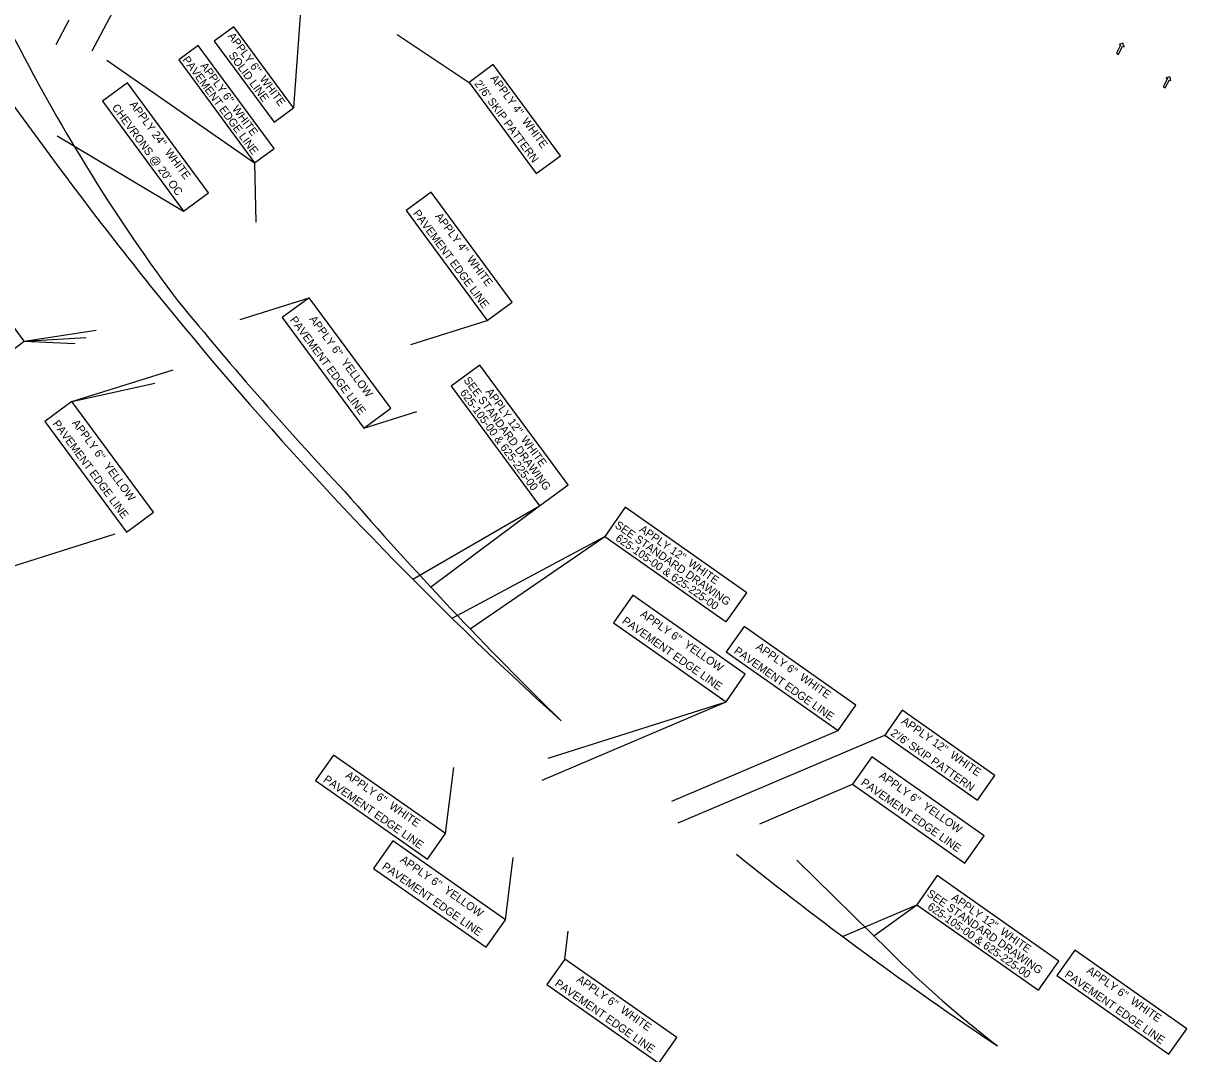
# Model space of a CAD drawing. Extents: x 1966013 to 1974896, y 789499 to 804826.
# Drawn here: x 1971229 to 1972392, y 795072 to 796102 of the extents above; entities that cross this region are included whole.
import ezdxf

# ---------------------------------------------------------------- set-up
doc = ezdxf.new("R2010")
doc.units = 0
for name, color, linetype in [('RD_EX_H2O_BlueLn', 7, 'Continuous'), ('RD_PD_ALT5_CL', 7, 'Continuous'), ('RD_PD_Final_Cl', 7, 'Continuous'), ('RD_PD_Final_LnLine', 7, 'Continuous')]:
    doc.layers.add(name, color=color, linetype=linetype)

msp = doc.modelspace()

# ---------------------------------------------------------------- linework, layer by layer
at = {"layer": 'RD_EX_H2O_BlueLn'}
for p, q in [((1971510.5, 796174.4), (1971499.1, 796017.7)), ((1971297.7, 796074.5), (1971318, 796113.1)), ((1971261.7, 796081), (1971274.7, 796105.7)), ((1971602.8, 796091.1), (1971674.5, 796043.1)), ((1971312.5, 796065.2), (1971460.2, 795962.6)), ((1971262.9, 795989.7), (1971389.1, 795914.2)), ((1971460.2, 795962.6), (1971461.4, 795903.2)), ((1971445.6, 795806.1), (1971514.7, 795827.8)), ((1971616.4, 795780.9), (1971692.7, 795804.9)), ((1971230, 795784.3), (1971301.7, 795795.5)), ((1971230, 795784.3), (1971291.8, 795788.1)), ((1971230, 795784.3), (1971280.7, 795782.2)), ((1971277.5, 795723.9), (1971378.9, 795755.8)), ((1971277.5, 795723.9), (1971360.6, 795742.4)), ((1971569.2, 795697.4), (1971622.3, 795714.1)), ((1971618.2, 795546.4), (1971744.8, 795619.8)), ((1971636.1, 795538.5), (1971744.8, 795619.8)), ((1971215.6, 795558.5), (1971320.9, 795591.6)), ((1971657.7, 795507.4), (1971810.1, 795589.2)), ((1971675.5, 795496.6), (1971810.1, 795589.2)), ((1971747.5, 795345.6), (1971931.4, 795423.9)), ((1971753.7, 795367.5), (1971931.4, 795423.9)), ((1971877.2, 795324.3), (1972043.3, 795395)), ((1971883.4, 795302.7), (1972089.9, 795390.6)), ((1971650.9, 795292), (1971659.2, 795358.1)), ((1971965.2, 795301.9), (1972057.7, 795341.3)), ((1971710.8, 795205.8), (1971718.7, 795268.2)), ((1972047.7, 795189.3), (1972121.9, 795220.9)), ((1972079, 795189.7), (1972121.9, 795220.9)), ((1971770.2, 795166.6), (1971773.7, 795194.4))]:
    msp.add_line(p, q, dxfattribs=at)
for points in [[(1971419.9, 796084.4), (1971479.7, 796003.4), (1971499.1, 796017.7), (1971439.3, 796098.8)], [(1971384.3, 796065.7), (1971460.2, 795962.6), (1971479.7, 795976.9), (1971403.7, 796080)], [(1971674.5, 796043.1), (1971741.7, 795951.9), (1971765.9, 795969.8), (1971698.7, 796061)], [(1971308, 796024.2), (1971389.1, 795914.2), (1971414.2, 795932.7), (1971333.1, 796042.7)], [(1971611.6, 795914.9), (1971692.7, 795804.9), (1971717.7, 795823.4), (1971636.6, 795933.4)], [(1971125.5, 795869.8), (1971203.1, 795764.5), (1971230, 795784.3), (1971152.4, 795889.6)], [(1971487.7, 795807.9), (1971569.2, 795697.4), (1971596.2, 795717.3), (1971514.7, 795827.8)], [(1971656.6, 795739.4), (1971744.8, 795619.8), (1971773.4, 795640.9), (1971685.2, 795760.4)], [(1971250.5, 795704.1), (1971332, 795593.5), (1971359, 795613.4), (1971277.5, 795723.9)], [(1971810.1, 795589.2), (1971931.6, 795503.8), (1971952.1, 795532.9), (1971830.5, 795618.3)], [(1971819, 795502.9), (1971931.4, 795423.9), (1971950.6, 795451.3), (1971838.2, 795530.3)], [(1971931.4, 795473.6), (1972043.3, 795395), (1972061.2, 795420.5), (1971949.3, 795499.1)], [(1972089.9, 795390.6), (1972182.6, 795325.5), (1972199.9, 795350.2), (1972107.2, 795415.3)], [(1971521.1, 795345.1), (1971633, 795266.5), (1971650.9, 795292), (1971539, 795370.6)], [(1972057.7, 795341.3), (1972170.1, 795262.4), (1972189.4, 795289.8), (1972077, 795368.7)], [(1971579.1, 795257.3), (1971691.6, 795178.4), (1971710.8, 795205.8), (1971598.4, 795284.7)], [(1972121.9, 795220.9), (1972243.5, 795135.5), (1972263.9, 795164.6), (1972142.3, 795250)], [(1972262, 795150), (1972373.8, 795071.4), (1972391.8, 795096.9), (1972279.9, 795175.5)], [(1971752.3, 795141.1), (1971864.1, 795062.5), (1971882, 795088), (1971770.2, 795166.6)]]:
    msp.add_lwpolyline(points, close=True, dxfattribs=at)
at = {"layer": 'RD_PD_ALT5_CL'}
msp.add_arc((1974296, 798203.9), 3760.7, 219.1113, 223.1115, dxfattribs=at)
at = {"layer": 'RD_PD_Final_Cl'}
for points in [[(1972321.4, 796072.2), (1972323.5, 796071.1), (1972327.7, 796079.2), (1972329.2, 796078.5), (1972328, 796082.3), (1972324.2, 796081.1), (1972325.6, 796080.3)], [(1972368.2, 796038.7), (1972370.3, 796037.6), (1972374.5, 796045.8), (1972376, 796045), (1972374.8, 796048.8), (1972371, 796047.6), (1972372.4, 796046.9)]]:
    msp.add_lwpolyline(points, close=True, dxfattribs=at)
at = {"layer": 'RD_PD_Final_LnLine'}
for p, q in [((1971183.3, 796068.4), (1971259.3, 795965.3)), ((1972094.9, 795174), (1972002.1, 795265.5))]:
    msp.add_line(p, q, dxfattribs=at)
for centre, radius, start, end in [((1972855.7, 796921.2), 1836, 206.8053, 216.4039), ((1974296, 798203.9), 3772.7, 216.3977, 219.8973), ((1974296, 798203.9), 3760.7, 219.1113, 223.1115), ((1974296, 798203.9), 3772.7, 219.8973, 227.8993), ((1974398.1, 798103.1), 3769, 220.9238, 225.7191), ((1974296, 798203.9), 3760.7, 231.2408, 236.1738), ((1972948.6, 796040), 1216, 225.4115, 232.1534)]:
    msp.add_arc(centre, radius, start, end, dxfattribs=at)

# ---------------------------------------------------------------- texts
at = {"layer": 'RD_EX_H2O_BlueLn'}
for s, height, rotation, p in [("APPLY 6''  WHITE", 8, 306.3977, (1971433, 796089.3)), ('PAVEMENT EDGE LINE', 8, 306.3977, (1971387.6, 796065.7)), ('SOLID LINE', 8, 306.3977, (1971433.7, 796070.2)), ("APPLY 6''  WHITE", 8, 306.3977, (1971405.5, 796059.5)), ("2'/6' SKIP PATTERN", 7.999, 306.3979, (1971679.4, 796041.8)), ("APPLY 4''  WHITE", 7.999, 306.3979, (1971695.3, 796047.1)), ("CHEVRONS @ 20' OC", 8, 306.3977, (1971317.1, 796017.9)), ("APPLY 24''  WHITE", 8, 306.3977, (1971334.8, 796020.9)), ('PAVEMENT EDGE LINE', 8, 306.3977, (1971618.1, 795912.1)), ("APPLY 4''  WHITE", 8, 306.3977, (1971640.2, 795909.1)), ('PAVEMENT EDGE LINE', 8, 306.3977, (1971495, 795805.6)), ("APPLY 6''  YELLOW", 8, 306.3977, (1971514.4, 795806.3)), ('SEE STANDARD DRAWING', 8, 306.3977, (1971668.6, 795745.3)), ('625-105-00 & 625-225-00', 8, 306.3977, (1971665, 795732.7)), ("APPLY 12''  WHITE", 8, 306.3977, (1971690.6, 795733.7)), ('PAVEMENT EDGE LINE', 8, 306.3977, (1971257.9, 795701.8)), ("APPLY 6''  YELLOW", 8, 306.3977, (1971277.2, 795702.5)), ('SEE STANDARD DRAWING', 8, 324.9236, (1971819.5, 795598.7)), ('625-105-00 & 625-225-00', 8, 324.9236, (1971820.1, 795585.6)), ("APPLY 12''  WHITE", 8, 324.9236, (1971844, 795594.7)), ('PAVEMENT EDGE LINE', 8, 324.9236, (1971826.7, 795503)), ("APPLY 6''  YELLOW", 8, 324.9236, (1971844.8, 795509.8)), ('PAVEMENT EDGE LINE', 8, 324.9236, (1971938.5, 795473)), ("APPLY 6''  WHITE", 8, 324.9236, (1971960.5, 795477.1)), ("APPLY 12''  WHITE", 7.999, 324.9238, (1972105.9, 795402.8)), ("2'/6' SKIP PATTERN", 7.999, 324.9238, (1972095, 795390.9)), ('PAVEMENT EDGE LINE', 8, 324.9236, (1971528.2, 795344.5)), ("APPLY 6''  WHITE", 8, 324.9236, (1971550.2, 795348.6)), ('PAVEMENT EDGE LINE', 8, 324.9236, (1972065.4, 795341.4)), ("APPLY 6''  YELLOW", 8, 324.9236, (1972083.5, 795348.3)), ("APPLY 6''  YELLOW", 8, 324.9236, (1971605, 795264.3)), ('PAVEMENT EDGE LINE', 8, 324.9236, (1971586.8, 795257.4)), ('SEE STANDARD DRAWING', 8, 324.9236, (1972131.3, 795230.3)), ("APPLY 12''  WHITE", 8, 324.9236, (1972155.9, 795226.3)), ('625-105-00 & 625-225-00', 8, 324.9236, (1972131.9, 795217.3)), ("APPLY 6''  WHITE", 8, 324.9236, (1971781.3, 795144.6)), ('PAVEMENT EDGE LINE', 8, 324.9236, (1972269.1, 795149.4)), ("APPLY 6''  WHITE", 8, 324.9236, (1972291, 795153.5)), ('PAVEMENT EDGE LINE', 8, 324.9236, (1971759.4, 795140.5))]:
    msp.add_text(s, height=height, rotation=rotation, dxfattribs=at).set_placement(p)

doc.saveas('drawing.dxf')
